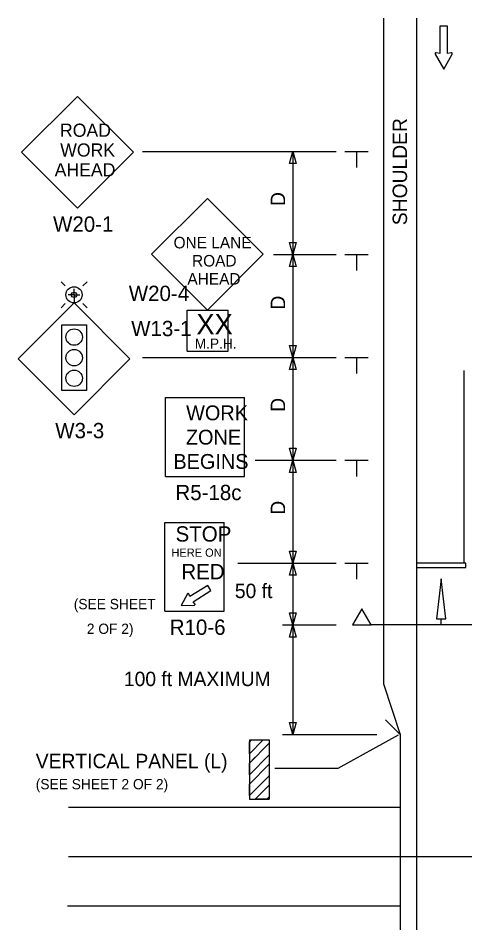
# Model space of a CAD drawing. Extents: x 16520 to 18479, y 5662 to 6927.
# Drawn here: x 16736.4 to 16953.3, y 6459.8 to 6899.4 of the extents above; entities that cross this region are included whole.
import ezdxf

# ---------------------------------------------------------------- set-up
doc = ezdxf.new("R2010")
doc.units = 0
for name, color, linetype in [('ALI_LEGAL_EX', 7, 'Continuous'), ('MT_SCRATCH_LEVEL_E', 7, 'Continuous'), ('PAVT_EDGE_EX', 7, 'Continuous'), ('TRAFFIC_SIGNS_PR', 7, 'Continuous'), ('TYPICAL_TEXT_DIMEN_PR', 7, 'Continuous')]:
    doc.layers.add(name, color=color, linetype=linetype)

msp = doc.modelspace()

# ---------------------------------------------------------------- linework, layer by layer
at = {"layer": 'ALI_LEGAL_EX'}
msp.add_lwpolyline([(16952.78, 6728.2), (16952.78, 6634.57)], dxfattribs=at)
at = {"layer": 'MT_SCRATCH_LEVEL_E'}
for p, q in [((16944.86, 6895.47), (16941.11, 6895.47)), ((16941.11, 6895.47), (16941.11, 6882.21)), ((16944.86, 6895.47), (16941.11, 6895.47)), ((16941.11, 6895.47), (16941.11, 6882.21)), ((16944.86, 6882.21), (16944.86, 6895.47)), ((16944.86, 6882.21), (16944.86, 6895.47)), ((16938.86, 6881.84), (16943, 6874.6)), ((16938.86, 6881.84), (16943, 6874.6)), ((16941.11, 6882.21), (16939.34, 6882.53)), ((16941.11, 6882.21), (16939.34, 6882.53)), ((16943, 6874.6), (16947.12, 6881.84)), ((16943, 6874.6), (16947.12, 6881.84)), ((16946.63, 6882.53), (16944.86, 6882.21)), ((16946.63, 6882.53), (16944.86, 6882.21))]:
    msp.add_line(p, q, dxfattribs=at)
for centre, start, end in [((16939.27, 6882.06), 80.0362, 209.7731), ((16939.27, 6882.06), 80.0362, 209.7731), ((16946.71, 6882.07), 330.4248, 99.9638), ((16946.71, 6882.07), 330.4248, 99.9638)]:
    msp.add_arc(centre, 0.463, start, end, dxfattribs=at)
at = {"layer": 'PAVT_EDGE_EX'}
for p, q in [((16913.78, 6899.43), (16913.78, 6576.06)), ((16929.78, 6899.43), (16929.78, 6077.5)), ((16913.78, 6576.06), (16921.78, 6551.35)), ((16921.78, 6551.35), (16914.71, 6558.43)), ((16921.78, 6551.35), (16921.78, 6419.96)), ((16760.93, 6516.09), (16921.78, 6516.09)), ((16760.93, 6492.09), (17256.97, 6492.09)), ((16760.41, 6468.09), (16921.78, 6468.09))]:
    msp.add_line(p, q, dxfattribs=at)
for points in [[(16760.93, 6492.09), (16785.93, 6492.09)], [(16860.93, 6492.09), (16885.93, 6492.09)]]:
    msp.add_lwpolyline(points, dxfattribs=at)
at = {"layer": 'TRAFFIC_SIGNS_PR'}
for p, q in [((16765.18, 6861.36), (16738.02, 6834.21)), ((16792.33, 6834.21), (16765.18, 6861.36)), ((16738.02, 6834.21), (16765.18, 6807.06)), ((16765.18, 6807.06), (16792.33, 6834.21)), ((16828.28, 6811.82), (16801.12, 6784.67)), ((16855.43, 6784.67), (16828.28, 6811.82)), ((16801.12, 6784.67), (16828.28, 6757.52)), ((16828.28, 6757.52), (16855.43, 6784.67)), ((16759.26, 6769.27), (16757.23, 6771.3)), ((16767.82, 6769.27), (16769.85, 6771.3)), ((16763.54, 6764.98), (16763.54, 6767.86)), ((16763.54, 6761.05), (16736.39, 6733.89)), ((16763.54, 6764.98), (16760.66, 6764.98)), ((16763.54, 6764.98), (16763.54, 6761.05)), ((16763.54, 6764.98), (16766.42, 6764.98)), ((16790.69, 6733.89), (16763.54, 6761.05)), ((16759.26, 6760.7), (16757.23, 6758.67)), ((16769.85, 6758.67), (16767.82, 6760.7)), ((16818.52, 6757.53), (16838.37, 6757.53)), ((16818.52, 6737.68), (16818.52, 6757.53)), ((16838.37, 6737.68), (16838.37, 6757.53)), ((16818.52, 6737.68), (16838.37, 6737.68)), ((16736.39, 6733.89), (16763.54, 6706.74)), ((16763.54, 6706.74), (16790.69, 6733.89)), ((16807.95, 6676.66), (16807.95, 6715.06)), ((16807.95, 6715.06), (16846.35, 6715.06)), ((16846.35, 6676.66), (16846.35, 6715.06)), ((16807.95, 6676.66), (16846.35, 6676.66)), ((16807.62, 6654.42), (16836.42, 6654.42)), ((16807.62, 6611.22), (16807.62, 6654.42)), ((16822.02, 6654.42), (16822.02, 6654.42)), ((16836.42, 6611.22), (16836.42, 6654.42)), ((16807.62, 6611.22), (16836.42, 6611.22)), ((16941.78, 6604.57), (16941.78, 6607.59)), ((16999.78, 6604.57), (16907.78, 6604.57)), ((16848.65, 6548.76), (16858.25, 6548.76)), ((16848.65, 6548.76), (16848.65, 6519.96)), ((16848.65, 6547.67), (16849.74, 6548.76)), ((16848.65, 6542.01), (16855.4, 6548.76)), ((16848.65, 6548.76), (16858.25, 6548.76)), ((16848.65, 6548.76), (16848.65, 6519.96)), ((16848.65, 6547.67), (16849.74, 6548.76)), ((16848.65, 6542.01), (16855.4, 6548.76)), ((16848.65, 6537.49), (16858.25, 6547.09)), ((16848.65, 6537.49), (16858.25, 6547.09)), ((16858.25, 6548.76), (16858.25, 6519.96)), ((16858.25, 6548.76), (16858.25, 6519.96)), ((16848.65, 6531.83), (16858.25, 6541.43)), ((16848.65, 6531.83), (16858.25, 6541.43)), ((16848.65, 6527.3), (16858.25, 6536.9)), ((16848.65, 6527.3), (16858.25, 6536.9)), ((16850.07, 6538.9), (16851.48, 6540.31)), ((16850.07, 6538.9), (16851.48, 6540.31)), ((16848.65, 6521.65), (16858.25, 6531.25)), ((16848.65, 6521.65), (16858.25, 6531.25)), ((16851.49, 6519.96), (16858.25, 6526.72)), ((16851.49, 6519.96), (16858.25, 6526.72)), ((16848.65, 6519.96), (16858.25, 6519.96)), ((16848.65, 6519.96), (16858.25, 6519.96)), ((16857.15, 6519.96), (16858.25, 6521.06)), ((16857.15, 6519.96), (16858.25, 6521.06))]:
    msp.add_line(p, q, dxfattribs=at)
for points in [[(16769.6, 6718.44), (16757.6, 6718.44), (16757.6, 6750.44), (16769.6, 6750.44)], [(16929.78, 6634.57), (16929.78, 6632.57), (16953.78, 6632.57), (16953.78, 6634.57)], [(16944.03, 6607.59), (16941.78, 6627.01), (16939.53, 6607.59)], [(16907.78, 6604.57), (16903.28, 6612.37), (16898.78, 6604.57)], [(16849.74, 6548.76), (16855.4, 6548.76), (16848.65, 6542.01), (16848.65, 6547.67)], [(16849.74, 6548.76), (16855.4, 6548.76), (16848.65, 6542.01), (16848.65, 6547.67)], [(16848.65, 6537.49), (16858.25, 6547.09), (16858.25, 6541.43), (16848.65, 6531.83)], [(16848.65, 6537.49), (16858.25, 6547.09), (16858.25, 6541.43), (16848.65, 6531.83)], [(16848.65, 6527.3), (16858.25, 6536.9), (16858.25, 6531.25), (16848.65, 6521.65)], [(16848.65, 6527.3), (16858.25, 6536.9), (16858.25, 6531.25), (16848.65, 6521.65)], [(16858.25, 6526.72), (16858.25, 6521.06), (16857.15, 6519.96), (16851.49, 6519.96)], [(16858.25, 6526.72), (16858.25, 6521.06), (16857.15, 6519.96), (16851.49, 6519.96)]]:
    msp.add_lwpolyline(points, close=True, dxfattribs=at)
for points in [[(16822.22, 6614.87), (16821.3, 6615.9), (16829.95, 6621.26), (16828.44, 6623.7), (16819.78, 6618.34), (16819.27, 6619.63)], [(16818.63, 6619.67), (16815.58, 6614.03), (16821.97, 6614.28)]]:
    msp.add_lwpolyline(points, dxfattribs=at)
for centre, radius in [((16763.54, 6764.98), 3.94), ((16763.54, 6764.98), 1.28), ((16763.6, 6744.44), 4), ((16763.6, 6734.44), 4), ((16763.6, 6724.44), 4)]:
    msp.add_circle(centre, radius, dxfattribs=at)
for centre, radius, start, end in [((16818.94, 6619.5), 0.355, 21.7152, 151.4266), ((16821.96, 6614.63), 0.354, 272.1787, 41.9178)]:
    msp.add_arc(centre, radius, start, end, dxfattribs=at)
at = {"layer": 'TYPICAL_TEXT_DIMEN_PR'}
for p, q in [((16796.7, 6834.57), (16890.78, 6834.57)), ((16868.21, 6828.71), (16869.78, 6834.57)), ((16869.78, 6834.57), (16869.78, 6784.57)), ((16869.78, 6834.57), (16871.35, 6828.71)), ((16895.03, 6834.57), (16906.28, 6834.57)), ((16900.66, 6834.57), (16900.66, 6826.79)), ((16869.78, 6828.71), (16868.21, 6828.71)), ((16871.35, 6828.71), (16869.78, 6828.71)), ((16869.78, 6784.57), (16868.21, 6790.43)), ((16868.21, 6790.43), (16869.78, 6790.43)), ((16869.78, 6784.57), (16868.21, 6790.43)), ((16868.21, 6790.43), (16869.78, 6790.43)), ((16869.78, 6790.43), (16871.35, 6790.43)), ((16871.35, 6790.43), (16869.78, 6784.57)), ((16869.78, 6790.43), (16871.35, 6790.43)), ((16871.35, 6790.43), (16869.78, 6784.57)), ((16860.36, 6784.57), (16890.78, 6784.57)), ((16868.21, 6778.71), (16869.78, 6784.57)), ((16869.78, 6784.57), (16869.78, 6734.57)), ((16869.78, 6784.57), (16871.35, 6778.71)), ((16895.03, 6784.57), (16906.28, 6784.57)), ((16900.66, 6784.57), (16900.66, 6776.79)), ((16869.78, 6778.71), (16868.21, 6778.71)), ((16871.35, 6778.71), (16869.78, 6778.71)), ((16869.78, 6734.57), (16868.21, 6740.43)), ((16868.21, 6740.43), (16869.78, 6740.43)), ((16869.78, 6740.43), (16871.35, 6740.43)), ((16871.35, 6740.43), (16869.78, 6734.57)), ((16796.7, 6734.57), (16890.78, 6734.57)), ((16868.21, 6728.71), (16869.78, 6734.57)), ((16869.78, 6734.57), (16871.35, 6728.71)), ((16869.78, 6734.57), (16869.78, 6684.57)), ((16895.03, 6734.57), (16906.28, 6734.57)), ((16900.66, 6734.57), (16900.66, 6726.79)), ((16869.78, 6728.71), (16868.21, 6728.71)), ((16871.35, 6728.71), (16869.78, 6728.71)), ((16869.78, 6684.57), (16868.21, 6690.43)), ((16868.21, 6690.43), (16869.78, 6690.43)), ((16869.78, 6690.43), (16871.35, 6690.43)), ((16871.35, 6690.43), (16869.78, 6684.57)), ((16851.42, 6684.57), (16890.78, 6684.57)), ((16868.21, 6678.71), (16869.78, 6684.57)), ((16869.78, 6684.57), (16869.78, 6634.57)), ((16869.78, 6684.57), (16871.35, 6678.71)), ((16895.03, 6684.57), (16906.28, 6684.57)), ((16900.66, 6684.57), (16900.66, 6676.79)), ((16869.78, 6678.71), (16868.21, 6678.71)), ((16871.35, 6678.71), (16869.78, 6678.71)), ((16869.78, 6634.57), (16868.21, 6640.43)), ((16868.21, 6640.43), (16869.78, 6640.43)), ((16869.78, 6640.43), (16871.35, 6640.43)), ((16871.35, 6640.43), (16869.78, 6634.57)), ((16843.07, 6634.57), (16890.78, 6634.57)), ((16868.21, 6628.71), (16869.78, 6634.57)), ((16869.78, 6634.57), (16869.78, 6604.57)), ((16869.78, 6634.57), (16871.35, 6628.71)), ((16895.03, 6634.57), (16906.28, 6634.57)), ((16900.66, 6634.57), (16900.66, 6626.79)), ((16869.78, 6628.71), (16868.21, 6628.71)), ((16871.35, 6628.71), (16869.78, 6628.71)), ((16869.78, 6604.57), (16868.21, 6610.43)), ((16868.21, 6610.43), (16869.78, 6610.43)), ((16869.78, 6610.43), (16871.35, 6610.43)), ((16871.35, 6610.43), (16869.78, 6604.57)), ((16864.78, 6604.57), (16890.78, 6604.57)), ((16868.21, 6598.71), (16869.78, 6604.57)), ((16869.78, 6604.57), (16871.35, 6598.71)), ((16869.78, 6604.57), (16869.78, 6551.35)), ((16869.78, 6598.71), (16868.21, 6598.71)), ((16871.35, 6598.71), (16869.78, 6598.71)), ((16869.78, 6551.35), (16868.21, 6557.22)), ((16868.21, 6557.22), (16869.78, 6557.22)), ((16869.78, 6557.22), (16871.35, 6557.22)), ((16871.35, 6557.22), (16869.78, 6551.35)), ((16864.78, 6551.35), (16910.48, 6551.35)), ((16920.82, 6551.01), (16891.56, 6534.78)), ((16920.82, 6551.01), (16891.56, 6534.78)), ((16891.56, 6534.78), (16860.98, 6534.78)), ((16891.56, 6534.78), (16860.98, 6534.78))]:
    msp.add_line(p, q, dxfattribs=at)

# ---------------------------------------------------------------- texts
at = {"layer": 'TRAFFIC_SIGNS_PR'}
for s, height, p in [('ROAD', 6.4, (16756.72, 6841.74)), ('WORK', 6.4, (16756.83, 6832.14)), ('AHEAD', 6.4, (16754.14, 6822.54)), ('W20-1', 7.44, (16753.35, 6795.62)), ('ONE LANE', 5.6, (16811.86, 6787.54)), ('ROAD', 5.6, (16820.81, 6778.74)), ('AHEAD', 5.6, (16818.57, 6769.94)), ('W20-4', 7.44, (16790.11, 6761.97)), ('W13-1', 7.44, (16791.28, 6744.9)), ('XX', 9.925, (16822.92, 6745.74)), ('M.P.H.', 4.961, (16822.14, 6738.78)), ('WORK', 7.217, (16817.95, 6704.03)), ('W3-3', 7.44, (16754.41, 6695.3)), ('ZONE', 7.217, (16817.83, 6692.22)), ('BEGINS', 7.217, (16811.76, 6680.41)), ('R5-18c', 7.44, (16812.76, 6665.22)), ('STOP', 7.44, (16812.82, 6645.08)), ('HERE ON', 4, (16810.83, 6637.72)), ('RED', 7.44, (16815.63, 6626.77)), ('R10-6', 7.44, (16810, 6599.78))]:
    msp.add_text(s, height=height, dxfattribs=at).set_placement(p)
at = {"layer": 'TYPICAL_TEXT_DIMEN_PR'}
for s, p in [('SHOULDER', (16925.2, 6798.81)), ('D', (16866, 6808.14)), ('D', (16866, 6757.8)), ('D', (16866, 6708.14)), ('D', (16866, 6658.14))]:
    msp.add_text(s, height=7, rotation=90, dxfattribs=at).set_placement(p)
for s, height, p in [('50 ft', 7, (16841.61, 6617.64)), ('(SEE SHEET', 5, (16763.41, 6612.24)), ('2 OF 2)', 5, (16769.75, 6600.24)), ('100 ft MAXIMUM', 7, (16787.74, 6574.88)), ('VERTICAL PANEL (L)', 7, (16744.95, 6534.99)), ('VERTICAL PANEL (L)', 7, (16744.95, 6534.99)), ('(SEE SHEET 2 OF 2)', 5, (16744.95, 6524.74)), ('(SEE SHEET 2 OF 2)', 5, (16744.95, 6524.74))]:
    msp.add_text(s, height=height, dxfattribs=at).set_placement(p)

doc.saveas('drawing.dxf')
